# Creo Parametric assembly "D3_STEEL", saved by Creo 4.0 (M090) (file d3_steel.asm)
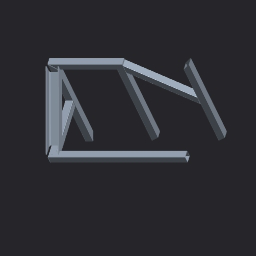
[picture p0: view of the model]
Units: Custom; MM, KILOGRAM, SECS

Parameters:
  BUW_PROJECT_REP_LEVEL = "DETAIL"
  PROJECT_SHORT = "d3"
  JOINT_32 = "GEHRUNG 1_889 END_SURFACE 1_879 START_SURFACE"
  JOINT_33 = "GEHRUNG 1_889 START_SURFACE 1_899 START_SURFACE"
  JOINT_37 = "T_STOSS 1_916 START_SURFACE 1_899"
  JOINT_38 = "GEHRUNG 1_943 START_SURFACE 1_953 END_SURFACE"
  JOINT_43 = "T_STOSS 1_933 END_SURFACE 1_953"
  JOINT_44 = "T_STOSS 1_953 START_SURFACE 1_879"
  JOINT_46 = "T_STOSS 1_916 END_SURFACE 1_963"

Other parameters: PROFILE_NUMBER, JOINT_NUMBER, CONNECT_EQUIP_NUMBER, EFX_ITEM_NR_SAME_COUNT_PRT_ASM, EFX_ITEM_NR_SAME_FOR_IDENT_MDL, EFX_ITEM_NR_SAME_FOR_STD_MDL, EFX_ITEM_NR_PART_START, EFX_ITEM_NR_PART_STD_START, EFX_ITEM_NR_PART_INCREMENT, EFX_ITEM_NR_ASM_START, EFX_ITEM_NR_ASM_STD_START, EFX_ITEM_NR_ASM_INCREMENT, SUBASM_NUMBER, EFX_ITEM_NR_ASM_COUNT, EFX_ITEM_NR_PART_COUNT, EFX_ITEM_NR_ASM_STD_COUNT, EFX_ITEM_NR_PART_STD_COUNT, X2, Y2, X3, Y3, X1

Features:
  1. datum plane "A_YZ"
  2. datum plane "A_XZ"
  3. datum plane "A_XY"
  4. coordinate system
  5. curve
  6. datum plane "ADTM1"
  7. datum plane "ADTM2"
  8. curve
  9. pattern
  10. curve
  11. curve
  12. curve
  13. datum point "APNT18"
  14. datum point "DATUM_POINT_ID_799"
  15. group "PROFIL_REF_CSYS"
  16. datum point "APNT22"
  17. coordinate system "ACS1"
  18. coordinate system "ACS2"
  19. datum point "APNT23"
  20. component "D3_SQUARE_TUBE_48"
  21. group "PROFIL_REF_CSYS_1"
  22. datum point "APNT24"
  23. coordinate system "ACS3"
  24. coordinate system "ACS4"
  25. datum point "APNT25"
  26. component "D3_SQUARE_TUBE_49"
  27. group "PROFIL_REF_CSYS_2"
  28. datum point "APNT26"
  29. coordinate system "ACS5"
  30. coordinate system "ACS6"
  31. datum point "APNT27"
  32. component "D3_SQUARE_TUBE_50"
  33. group "CURVE_2PNTS_1_1"
  34. datum point "Datum Point id 901"
  35. datum curve "Curve 1"
  36. group "PROFIL_REF_CSYS_3"
  37. datum point "APNT30"
  38. coordinate system "ACS7"
  39. coordinate system "ACS8"
  40. datum point "APNT31"
  41. component "D3_SQUARE_TUBE_51"
  42. group "CURVE_2PNTS_1_1_1"
  43. datum point "Datum Point id 918"
  44. datum curve "Curve 2"
  45. group "PROFIL_REF_CSYS_4"
  46. datum point "APNT34"
  47. coordinate system "ACS9"
  48. coordinate system "ACS10"
  49. datum point "APNT35"
  50. component "D3_U_BEAM_PARALLEL_52"
  51. group "PROFIL_REF_CSYS_5"
  52. datum point "APNT36"
  53. coordinate system "ACS11"
  54. coordinate system "ACS12"
  55. datum point "APNT37"
  56. component "D3_SQUARE_TUBE_53"
  57. group "PROFIL_REF_CSYS_6"
  58. datum point "APNT38"
  59. coordinate system "ACS13"
  60. coordinate system "ACS14"
  61. datum point "APNT39"
  62. component "D3_SQUARE_TUBE_54"
  63. group "PROFIL_REF_CSYS_7"
  64. datum point "APNT40"
  65. coordinate system "ACS15"
  66. coordinate system "ACS16"
  67. datum point "APNT41"
  68. component "D3_SQUARE_TUBE_50"

Other named items: ACS0

Named dimensions: T_PARAM, X_ROT, Z_ROT, X_OFF, Y_OFF, Z_OFF, T_PARAM1, T_PARAM2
